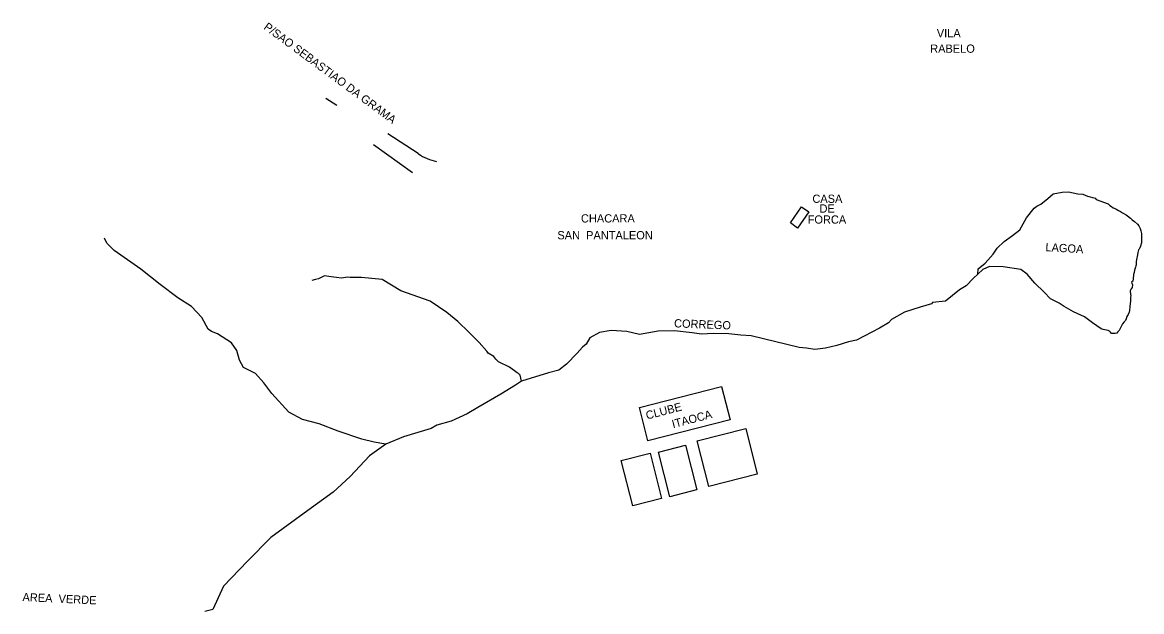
# Model space of a CAD drawing. Extents: x 325899 to 364828, y 7568995 to 7592502.
# Drawn here: x 329954 to 330498, y 7590123 to 7590410 of the extents above; entities that cross this region are included whole.
import ezdxf

# ---------------------------------------------------------------- set-up
doc = ezdxf.new("R2010")
doc.units = 0
for name, color, linetype in [('EDIFEXISTENT', 7, 'Continuous'), ('EDIFIDENTIF', 7, 'Continuous'), ('EDIFOBRAEXIS', 7, 'Continuous')]:
    doc.layers.add(name, color=color, linetype=linetype)

msp = doc.modelspace()

# ---------------------------------------------------------------- linework, layer by layer
at = {"layer": 'EDIFEXISTENT'}
for p, q in [((330326.95, 7590312.09), (330332.28, 7590319.91)), ((330335.85, 7590317.5), (330330.44, 7590309.59)), ((330332.28, 7590319.91), (330335.85, 7590317.5)), ((330330.44, 7590309.59), (330326.95, 7590312.09)), ((330253.52, 7590222.49), (330293.47, 7590232.71)), ((330293.47, 7590232.71), (330297.62, 7590216.48)), ((330257.66, 7590206.28), (330253.52, 7590222.49)), ((330297.62, 7590216.48), (330257.66, 7590206.28)), ((330281.57, 7590206.23), (330305.2, 7590212.27)), ((330305.2, 7590212.27), (330310.85, 7590190.17)), ((330287.21, 7590184.15), (330281.57, 7590206.23)), ((330262.82, 7590200.85), (330275.96, 7590204.21)), ((330268.38, 7590179.07), (330262.82, 7590200.85)), ((330275.96, 7590204.21), (330281.5, 7590182.5)), ((330244.66, 7590196.71), (330258.7, 7590200.3)), ((330250.28, 7590174.73), (330244.66, 7590196.71)), ((330258.7, 7590200.3), (330264.34, 7590178.25)), ((330310.85, 7590190.17), (330287.21, 7590184.15)), ((330281.26, 7590182.5), (330268.38, 7590179.07)), ((330281.28, 7590182.44), (330281.26, 7590182.5)), ((330281.5, 7590182.5), (330281.28, 7590182.44)), ((330264.34, 7590178.25), (330250.28, 7590174.73))]:
    msp.add_line(p, q, dxfattribs=at)
at = {"layer": 'EDIFOBRAEXIS'}
for points in [[(330106.48, 7590369.13), (330101.11, 7590372.58), (330102.11, 7590372.17)], [(330146.07, 7590345.78), (330131.34, 7590355.44)], [(330143.29, 7590336.48), (330124.23, 7590349.99)], [(330481.39, 7590259.95), (330478.97, 7590260.35), (330477.98, 7590260.65), (330473.73, 7590263.63), (330469.86, 7590266.48), (330464.51, 7590268.96), (330459.94, 7590271.6), (330457.58, 7590273.23), (330453.29, 7590275.3), (330450.24, 7590278.54), (330445.75, 7590282.92), (330442.05, 7590287.29), (330438.88, 7590289.5), (330430.39, 7590290.81), (330423.71, 7590290.88), (330420.39, 7590289.55), (330418.07, 7590287.28), (330418.13, 7590289.89), (330421.52, 7590292.54), (330425.42, 7590296.88), (330427.47, 7590299.85), (330430.79, 7590303.05), (330434.92, 7590305.96), (330438.49, 7590308.76), (330441.65, 7590314.61), (330445.45, 7590319.31), (330446.63, 7590320.2), (330448.68, 7590321.27), (330452.1, 7590324.01), (330454.72, 7590326.29), (330459.1, 7590327.12), (330462.18, 7590327.23), (330466.61, 7590326.33), (330469.1, 7590326.09), (330471.32, 7590325.19), (330475.06, 7590324.2), (330475.61, 7590323.53), (330481.39, 7590321.47)], [(330481.39, 7590321.47), (330482.27, 7590320.62), (330483.08, 7590320.02), (330483.89, 7590319.45), (330485.03, 7590318.93), (330485.58, 7590318.62), (330486.44, 7590318.18), (330487.4, 7590317.66), (330488.34, 7590317.1), (330490.13, 7590316.04), (330490.79, 7590315.52), (330492.27, 7590314.36), (330493, 7590313.64), (330494.16, 7590312.79), (330495.63, 7590311.53), (330496.35, 7590310.66), (330496.98, 7590309.46), (330497.3, 7590308.36), (330497.54, 7590306.91), (330497.55, 7590305.77), (330497.64, 7590304.65), (330497.63, 7590303.45), (330497.57, 7590302.46), (330497.09, 7590300.87), (330496.75, 7590299.98), (330496.44, 7590299.42), (330496.16, 7590298.99), (330495.95, 7590298.46), (330495.74, 7590297.68), (330495.57, 7590296.69), (330495.17, 7590294.33), (330494.98, 7590293.19), (330494.91, 7590291.69), (330494.88, 7590291.33), (330494.67, 7590290.6), (330494.18, 7590289.13), (330493.94, 7590288.09), (330493.67, 7590287), (330493.47, 7590284.99), (330493.31, 7590283.85), (330492.67, 7590283.53), (330492.89, 7590282.81), (330493.16, 7590282.1), (330493.07, 7590280.78), (330493, 7590280.75), (330492.48, 7590280.15), (330492.2, 7590279.54), (330492.01, 7590279.13), (330492.17, 7590277.4), (330492.32, 7590277.1), (330492.28, 7590275.68), (330492.24, 7590274.13), (330492.1, 7590272.98), (330491.96, 7590271.54), (330491.76, 7590269.55), (330491.52, 7590268.72), (330491.03, 7590267.68), (330490.49, 7590266.65), (330490.09, 7590265.56), (330489.73, 7590264.75), (330489.32, 7590264.17), (330489.19, 7590264.07), (330488.27, 7590263.04), (330487.49, 7590261.54), (330486.68, 7590259.82), (330486.55, 7590259.75), (330485.96, 7590258.99), (330485.52, 7590258.64), (330484.84, 7590258.37), (330484.07, 7590258.37), (330483.24, 7590258.5), (330482.9, 7590258.66), (330482.54, 7590259.1), (330482.1, 7590259.59), (330481.39, 7590259.95)], [(330130.21, 7590204.75), (330129.25, 7590204.79), (330124.56, 7590205.59), (330118.61, 7590207.1), (330107.1, 7590210.97), (330097.96, 7590214.47), (330089.83, 7590216.72), (330083.2, 7590220.14), (330074.89, 7590229.23), (330071.03, 7590234.39), (330066.9, 7590238.97), (330061.12, 7590241.97), (330059.24, 7590245.48), (330057.94, 7590250.17), (330055.35, 7590253.84), (330050.69, 7590256.88), (330048.4, 7590258.28), (330045.57, 7590259.37), (330043.86, 7590260.58), (330040.84, 7590266.22), (330035.88, 7590271.52), (330029.21, 7590275.73), (330020.66, 7590282.28), (330011.27, 7590289.72), (329998.29, 7590298.8), (329996.73, 7590300.22), (329994.6, 7590302.36), (329993.49, 7590304.74)], [(330418.07, 7590287.28), (330415.96, 7590285.37), (330412.4, 7590281.59), (330409.2, 7590279.55), (330402.26, 7590274.16), (330396.05, 7590273.41), (330395.48, 7590272.81), (330390.08, 7590271.21), (330382.34, 7590268.7), (330376.02, 7590265.23), (330374.65, 7590263.65), (330370.22, 7590260.94), (330359.11, 7590255.15), (330355.19, 7590254.4), (330349.55, 7590252.67), (330343.94, 7590251.35), (330338.77, 7590250.66), (330334.74, 7590251.26), (330331.11, 7590251.61), (330307.9, 7590257.32), (330302.8, 7590257.65), (330297.04, 7590258.32), (330289.62, 7590258.34), (330283.65, 7590258.02), (330279.16, 7590258.67), (330270.61, 7590259.68), (330262.73, 7590259.48), (330253.56, 7590257.94), (330247.46, 7590259.47), (330239.75, 7590259.83), (330234.07, 7590258.9), (330229.48, 7590256.29), (330227.64, 7590253.22), (330225.91, 7590251.85), (330223.23, 7590248.79), (330218.12, 7590243.52), (330214.3, 7590240.6), (330209.28, 7590239.33), (330196.21, 7590235.29), (330193.39, 7590233.3), (330186.11, 7590229.03), (330175.05, 7590222.56), (330169.75, 7590219.48), (330162.12, 7590215.88), (330155.08, 7590213.82), (330152.27, 7590212.26), (330145.81, 7590210.34), (330138.92, 7590208.23), (330130.21, 7590204.75), (330122.38, 7590199.06), (330112.94, 7590189.01), (330104.65, 7590181.33), (330092.36, 7590172.38), (330074.44, 7590159.32), (330063.1, 7590147.77), (330051.37, 7590135.74), (330046.22, 7590124.37), (330046.22, 7590124.37), (330046.22, 7590124.37), (330042.28, 7590123.36)], [(330196.21, 7590235.29), (330195.58, 7590238.11), (330194.8, 7590238.92), (330194.13, 7590239.24), (330190.46, 7590242.13), (330184.99, 7590244.67), (330183.71, 7590245.99), (330182.76, 7590247.22), (330180.04, 7590248.86), (330179.37, 7590249.78), (330175.72, 7590254.03), (330170.68, 7590259.03), (330165.29, 7590264.21), (330159.87, 7590268.55), (330151.82, 7590274.13), (330137.56, 7590279.16), (330128.54, 7590284.57), (330118.52, 7590285.62), (330112.9, 7590285.6), (330111.59, 7590285.72), (330108.71, 7590285.28), (330106.38, 7590285.64), (330103.69, 7590285.86), (330100.52, 7590286.38), (330097.6, 7590284.93), (330096.05, 7590284.64), (330094.29, 7590284.21)]]:
    msp.add_lwpolyline(points, dxfattribs=at)
msp.add_arc((330159.33, 7590364.31), 22.79, 234.3979, 259.0041, dxfattribs=at)

# ---------------------------------------------------------------- texts
at = {"layer": 'EDIFIDENTIF'}
for s, rotation, p in [('P/SAO SEBASTIAO DA GRAMA', 323.4881, (330070.59, 7590406.56)), ('VILA ', 359.9971, (330398.09, 7590402.29)), (' RABELO', 359.9971, (330393.39, 7590394.76)), ('LAGOA', 356.7317, (330450.81, 7590298.41)), ('CORREGO', 357.7636, (330270.33, 7590261.43)), ('CLUBE', 14.6669, (330257.23, 7590216.59)), ('ITAOCA', 14.6669, (330269.89, 7590212.42)), ('AREA  VERDE', 357.3992, (329953.62, 7590128.47))]:
    msp.add_text(s, height=4, rotation=rotation, dxfattribs=at).set_placement(p)
for s, p in [('CASA', (330337.62, 7590321.87)), ('DE', (330341.08, 7590317.12)), ('CHACARA', (330225.14, 7590312.33)), ('FORCA', (330335.33, 7590311.77)), ('SAN  PANTALEON', (330213.66, 7590304.16))]:
    msp.add_text(s, height=4, dxfattribs=at).set_placement(p)

doc.saveas('drawing.dxf')
